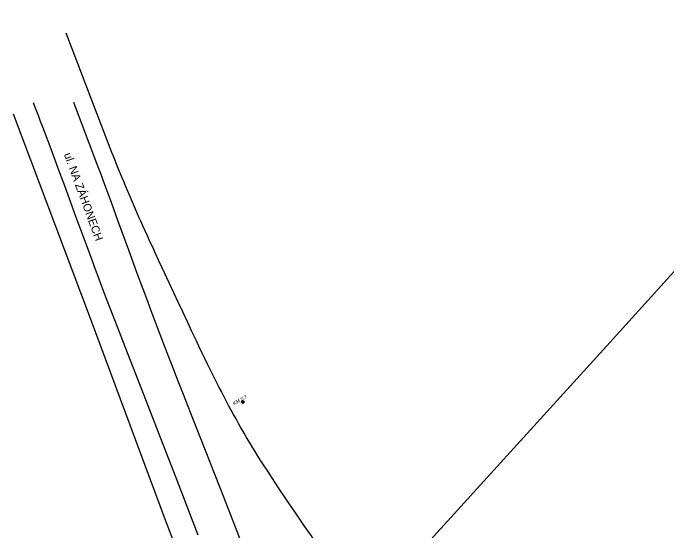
# Model space of a CAD drawing. Extents: x -540235 to -537963, y -1184915 to -1183660.
# Drawn here: x -538433.1 to -538311.8, y -1183819.9 to -1183723.8 of the extents above; entities that cross this region are included whole.
import ezdxf

# ---------------------------------------------------------------- set-up
doc = ezdxf.new("R2010")
doc.units = 0
for name, color, linetype in [('Vrstva 10', 7, 'Continuous'), ('Vrstva 13', 7, 'Continuous'), ('Vrstva 25', 7, 'Continuous'), ('Vrstva 40', 7, 'Continuous'), ('Vrstva 49', 7, 'Continuous'), ('Vrstva 7', 7, 'Continuous')]:
    doc.layers.add(name, color=color, linetype=linetype)

msp = doc.modelspace()

# ---------------------------------------------------------------- linework, layer by layer
at = {"layer": 'Vrstva 10'}
for p, q in [((-538421.859, -1183740.29), (-538417.58, -1183751.64)), ((-538423.55, -1183755.759), (-538421.468, -1183761.438)), ((-538414.83, -1183759.039), (-538413.677, -1183762.184)), ((-538413.677, -1183762.184), (-538411.668, -1183767.692)), ((-538413.417, -1183782.882), (-538411.913, -1183786.768)), ((-538405.55, -1183784.18), (-538404.878, -1183785.931)), ((-538411.913, -1183786.768), (-538409.275, -1183793.564)), ((-538409.275, -1183793.564), (-538405.31, -1183803.756)), ((-538401.542, -1183794.506), (-538399.81, -1183798.91)), ((-538399.81, -1183798.91), (-538397.205, -1183805.513)), ((-538405.31, -1183803.756), (-538403.328, -1183808.852)), ((-538403.328, -1183808.852), (-538401.35, -1183813.95)), ((-538391.89, -1183819.108), (-538390.663, -1183822.28))]:
    msp.add_line(p, q, dxfattribs=at)
for points in [[(-538429.35, -1183740.37), (-538428.889, -1183741.553), (-538428.445, -1183742.701), (-538428.018, -1183743.813), (-538427.606, -1183744.892), (-538426.813, -1183746.984), (-538426.075, -1183748.947)], [(-538426.075, -1183748.947), (-538425.388, -1183750.789), (-538424.746, -1183752.517), (-538423.55, -1183755.759)], [(-538417.58, -1183751.64), (-538416.818, -1183753.67), (-538416.109, -1183755.575), (-538415.447, -1183757.362), (-538414.83, -1183759.039)], [(-538421.468, -1183761.438), (-538419.905, -1183765.697), (-538418.728, -1183768.889)], [(-538411.668, -1183767.692), (-538410.159, -1183771.822), (-538409.022, -1183774.917)], [(-538418.728, -1183768.889), (-538417.839, -1183771.281), (-538417.168, -1183773.073), (-538416.663, -1183774.416)], [(-538416.663, -1183774.416), (-538415.9, -1183776.429), (-538415.13, -1183778.44), (-538413.417, -1183782.882)], [(-538409.022, -1183774.917), (-538408.164, -1183777.236), (-538407.517, -1183778.975), (-538407.029, -1183780.277), (-538406.293, -1183782.23), (-538405.55, -1183784.18)], [(-538404.878, -1183785.931), (-538404.245, -1183787.571), (-538403.65, -1183789.108), (-538402.528, -1183791.988), (-538401.542, -1183794.506)], [(-538397.205, -1183805.513), (-538395.905, -1183808.816), (-538394.61, -1183812.12)], [(-538394.61, -1183812.12), (-538393.204, -1183815.726), (-538391.89, -1183819.108)], [(-538401.35, -1183813.95), (-538400.024, -1183817.38), (-538398.784, -1183820.596)]]:
    msp.add_lwpolyline(points, dxfattribs=at)
at = {"layer": 'Vrstva 13'}
for p, q in [((-538414.73, -1183749.62), (-538423.214, -1183727.526)), ((-538401.572, -1183779.219), (-538402.431, -1183777.382))]:
    msp.add_line(p, q, dxfattribs=at)
for points in [[(-538412.56, -1183755.037), (-538412.839, -1183754.363), (-538413.322, -1183753.182), (-538413.68, -1183752.294), (-538413.946, -1183751.627), (-538414.341, -1183750.625), (-538414.73, -1183749.62)], [(-538411.869, -1183756.684), (-538412.239, -1183755.806), (-538412.56, -1183755.037)], [(-538408.148, -1183765.109), (-538408.583, -1183764.151), (-538408.99, -1183763.252), (-538409.369, -1183762.408), (-538409.722, -1183761.617), (-538410.379, -1183760.13), (-538410.949, -1183758.827), (-538411.442, -1183757.685), (-538411.869, -1183756.684)], [(-538406.644, -1183768.377), (-538407.18, -1183767.218), (-538407.681, -1183766.13), (-538408.148, -1183765.109)], [(-538402.431, -1183777.382), (-538404.045, -1183773.942), (-538405.455, -1183770.931), (-538406.07, -1183769.613), (-538406.644, -1183768.377)], [(-538397.91, -1183787.024), (-538398.604, -1183785.568), (-538399.122, -1183784.473), (-538399.893, -1183782.828), (-538400.66, -1183781.18), (-538401.572, -1183779.219)], [(-538393.538, -1183795.745), (-538394.009, -1183794.849), (-538394.446, -1183794.006), (-538394.852, -1183793.214), (-538395.23, -1183792.47), (-538395.583, -1183791.772), (-538395.911, -1183791.116), (-538396.521, -1183789.884), (-538397.05, -1183788.803), (-538397.51, -1183787.855), (-538397.91, -1183787.024)], [(-538388.63, -1183804.412), (-538389.056, -1183803.71), (-538389.464, -1183803.028), (-538389.856, -1183802.365), (-538390.232, -1183801.722), (-538390.593, -1183801.097), (-538390.94, -1183800.49), (-538391.273, -1183799.902), (-538391.593, -1183799.33), (-538391.901, -1183798.775), (-538392.198, -1183798.237), (-538392.483, -1183797.714), (-538393.03, -1183796.7), (-538393.538, -1183795.745)], [(-538387.721, -1183805.878), (-538388.186, -1183805.134), (-538388.63, -1183804.412)], [(-538382.523, -1183813.796), (-538383.584, -1183812.212), (-538384.375, -1183811.021), (-538384.967, -1183810.125), (-538385.851, -1183808.779), (-538386.73, -1183807.43), (-538387.237, -1183806.643), (-538387.721, -1183805.878)], [(-538377.271, -1183821.446), (-538377.875, -1183820.581), (-538378.441, -1183819.769), (-538379.496, -1183818.243), (-538380.415, -1183816.904), (-538381.216, -1183815.729), (-538381.914, -1183814.699), (-538382.523, -1183813.796)]]:
    msp.add_lwpolyline(points, dxfattribs=at)
at = {"layer": 'Vrstva 25'}
for radius in [0.25, 0.0303]:
    msp.add_circle((-538390.45, -1183795.93), radius, dxfattribs=at)
at = {"layer": 'Vrstva 7'}
for p, q in [((-538322.96, -1183785.49), (-538267.21, -1183723.77)), ((-538433.07, -1183742.46), (-538418.8, -1183780.4)), ((-538418.8, -1183780.4), (-538404.88, -1183817.79)), ((-538360.04, -1183826.31), (-538322.96, -1183785.49)), ((-538404.88, -1183817.79), (-538381.5, -1183878.39))]:
    msp.add_line(p, q, dxfattribs=at)

# ---------------------------------------------------------------- texts
at = {"layer": 'Vrstva 40'}
msp.add_text('KM 0.7', height=0.65, rotation=28.373158, dxfattribs=at).set_placement((-538392.08, -1183796.538))
at = {"layer": 'Vrstva 49'}
msp.add_text('ul. NA ZÁHONECH', height=1.5, rotation=290.136967, dxfattribs=at).set_placement((-538423.682, -1183749.981))

doc.saveas('drawing.dxf')
